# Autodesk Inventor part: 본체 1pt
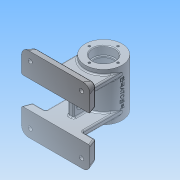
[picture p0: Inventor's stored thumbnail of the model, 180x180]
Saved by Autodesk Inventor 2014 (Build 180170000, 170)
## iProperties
Created: 2016-07
Part Number: 본체 1pt
Material: 알루미늄 6061
Document SubType Name: Modeling
Designer: NET
Density: 2.71 g/cm^3
Appearance: 알루미늄 - 평지
Mass: 499.72 g
Surface Area: 539.14 cm^2
Volume: 184.399 cm^3
Author: NET
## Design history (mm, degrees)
sketch "스케치1"
  geometry: C1 r 27 at (0, 0); 1 further point
  constraints: 1 centre point, 1 coincident
  dimensions: "d0" = 54 diameter of C1
extrude "돌출1" new body sketch "스케치1" stored distance "d1" = 70; taper "d2" = 0 deg
sketch "스케치2"
  geometry: C1 r 27 at (0, 0) reference; C2 r 16 at (0, 0)
  constraints: 1 centre point, 1 coincident
  dimensions: "d3" = 32 diameter of C2
extrude "돌출2" cut sketch "스케치2" distance "d4" = 12; taper "d5" = 0 deg
sketch "스케치3"
  geometry: C1 r 22 at (0, 0); 1 further point
  constraints: 1 centre point, 1 coincident
  dimensions: "d6" = 44 diameter of C1
extrude "돌출3" cut sketch "스케치3" stored distance "d7" = 42; taper "d8" = 0 deg
sketch "스케치4"
  geometry: C1 r 16 at (0, 0) reference; C2 r 14 at (0, 0)
  constraints: 1 centre point, 1 coincident
  dimensions: "d9" = 28 diameter of C2
extrude "돌출4" cut sketch "스케치4" stored distance "d10" = 42; taper "d11" = 0 deg
node "작업 평면2"
sketch "스케치5"
  geometry: L1 (-50, 55)-(50, 55); L2 (50, 55)-(50, 20); L3 (50, 20)-(-50, 20); L4 (-50, 20)-(-50, 55); L5 (-50, -20)-(50, -20); L6 (50, -20)-(50, -55); L7 (50, -55)-(-50, -55); L8 (-50, -55)-(-50, -20); L9 (-27, -20)-(27, -20); L10 (27, -20)-(27, -28); L11 (27, -28)-(-27, -28); L12 (-27, -28)-(-27, -20); L13 (-27, 20)-(27, 20); L14 (27, 20)-(27, 28); L15 (27, 28)-(-27, 28); L16 (-27, 28)-(-27, 20); 4 further points
  constraints: 32 end point, 8 parallel, 4 equal length, 4 horizontal, 4 midpoint, 4 perpendicular, 3 vertical alignment, 2 point on line
  dimensions: "d13" = 35 distance of L5.end L6.end; "d14" = 8 distance of L9.end L10.end; "d15" = 55 distance from line of point (0, 0) L1; "d16" = 100 distance between parallel lines of L2 L4; "d17" = 54 distance of L10.end L11.end; "d19" = 55 distance from line of point (0, 0) L7
extrude "돌출5" join sketch "스케치5" stored distance "d20" = 42; taper "d21" = 0 deg
sketch "스케치6"
  geometry: L1 (-40, 55)-(40, 55); L2 (50, 45)-(50, -45); L3 (40, -55)-(-40, -55); L4 (-50, -45)-(-50, 45); A1 r 10 centre (-40, -45) between (-50, -45) and (-40, -55); A2 r 10 centre (-40, 45) between (-40, 55) and (-50, 45); A3 r 10 centre (40, 45) between (50, 45) and (40, 55); A4 r 10 centre (40, -45) between (40, -55) and (50, -45); 7 further points
  constraints: 8 end point, 8 point on circle, 8 point on line, 8 tangent, 4 centre point, 3 equal radius, 2 midpoint, 2 parallel, 1 horizontal, 1 horizontal alignment, 1 perpendicular, 1 vertical alignment
  dimensions: "d22" = 100 distance of point (50, -55) point (-50, -55); "d23" = 110 distance of point (50, 55) point (50, -55); "d68" = 10 radius of A1
extrude "돌출6" join sketch "스케치6" distance "d24" = 12; taper "d25" = -20 deg
sketch "스케치7"
  geometry: L1 (-50, -45)-(-50, 45) reference; L2 (50, 45)-(50, -45) reference; L3 (-50, 20)-(50, 20); L4 (50, 20)-(50, -20); L5 (50, -20)-(-50, -20); L6 (-50, -20)-(-50, 20); 5 further points
  constraints: 8 end point, 2 parallel, 2 point on line, 1 horizontal, 1 perpendicular
extrude "돌출7" cut sketch "스케치7" distance "d26" = 12; taper "d27" = 0 deg
node "작업 평면3"
sketch "스케치8"
  geometry: L1 (27, 35)-(-27, 35) reference; C1 r 5 at (0, 13); 1 further point
  constraints: 1 centre point, 1 vertical alignment
  dimensions: "d29" = 22 distance from line of L1 C1.centre; "d30" = 10 diameter of C1
extrude "돌출8" join sketch "스케치8" stored distance "d31" = 12; taper "d32" = 0 deg
node "작업 평면4"
sketch "스케치9"
  geometry: L1 (-50, -20)-(50, -20) reference; L2 (50, 20)-(-50, 20) reference; L3 (-4, 20)-(4, 20); L4 (4, 20)-(4, -20); L5 (4, -20)-(-4, -20); L6 (-4, -20)-(-4, 20); 3 further points
  constraints: 8 end point, 2 midpoint, 2 parallel, 2 point on line, 1 coincident, 1 horizontal, 1 perpendicular
  dimensions: "d34" = 8 distance between parallel lines of L4 L6
extrude "돌출9" join sketch "스케치9" stored distance "d35" = 12; taper "d36" = 0 deg
sketch "스케치10"
  geometry: L1 (0, 21.298)-(40, 21.298) reference; L2 (12, 10)-(28, 10); L3 (12, 6.5)-(28, 6.5); L4 (28, 13.5)-(12, 13.5); L5 (65, -22)-(40, -22) reference; A1 r 3.5 centre (12, 10) between (12, 13.5) and (12, 6.5); A2 r 3.5 centre (28, 10) between (28, 6.5) and (28, 13.5); 4 further points
  constraints: 8 end point, 4 point on circle, 4 tangent, 2 centre point, 2 midpoint, 2 parallel, 1 vertical alignment
  dimensions: "d37" = 3.5 radius of A2; "d38" = 23 dimension on A2 A1; "d39" = 32 distance from line of L5 point (20, 10)
extrude "돌출10" cut sketch "스케치10" stored distance "d40" = 12; taper "d41" = 0 deg
sketch "스케치11"
  geometry: L1 (0, 0)-(-15.898, -25.441); L2 (0, 0)-(0, -16.13)
  constraints: 4 end point, 1 vertical
  dimensions: "d42" = 30 distance of L1.start L1.end; "d43" = 32 deg angle of L2 L1
node "작업 평면5"
sketch "스케치12"
  geometry: C1 r 6 at (0, 0); 1 further point
  constraints: 1 centre point, 1 coincident
  dimensions: "d44" = 12 diameter of C1
extrude "돌출11" join sketch "스케치12" stored distance "d45" = 12; taper "d46" = 0 deg
hole "구멍1" diameter "d49" = 6; stored, may be unused: countersink angle "d53" = 90 deg, drill point angle "d55" = 118 deg; dims "d47" = 12.5, "d48" = 1, "d50" = 6, "d51" = 10, "d52" = 4, "d54" = 8
node "작업 평면6"
sketch "스케치13"
  geometry: L1 (27, -35)-(27, 35) reference; 2 further points
  constraints: 1 coincident, 1 other
  dimensions: "d63" = 27 distance from line of point (0, 0) L1 (derived); "d64" = 35 vertical distance of L1.end point (0, 0) (derived)
feature "엠보싱1" sketch "스케치13" dims "d0" = 54, "d9" = 28, "d65" = 0.5, "d66" = 0
fillet "모깎기1" dims "d67" = 2
fillet "모깎기2" dims "d75" = 2
hole "구멍2" diameter "d78" = 5.188; stored, may be unused: countersink angle "d82" = 90 deg, drill point angle "d84" = 118 deg; dims "d76" = 10, "d77" = 10, "d79" = 6, "d80" = 10, "d81" = 4, "d83" = 8
hole "구멍3" diameter "d87" = 5.188; stored, may be unused: countersink angle "d91" = 90 deg, drill point angle "d93" = 118 deg; dims "d85" = 10, "d86" = 10, "d88" = 6, "d89" = 10, "d90" = 4, "d92" = 8
sketch "스케치14"
  geometry: C1 r 16 at (0, 0) reference; 1 further point
  constraints: 1 horizontal alignment
  dimensions: "d94" = 21 distance of C1.centre point (-21, 0)
hole "구멍4" sketch "스케치14" at (-21, 0) diameter "d95" = 3.242; stored, may be unused: countersink angle "d99" = 90 deg, drill point angle "d101" = 118 deg; dims "d96" = 8, "d97" = 10, "d98" = 4, "d100" = 10
chamfer "모따기1" distance "d105" = 1; stored, may be unused: second distance "d106" = 2, angle "d107" = 45 deg
fillet "모깎기3" dims "d108" = 3, "d109" = 0.3
fillet "모깎기4" dims "d110" = 2
node "솔리드1"
mirror "대칭1"
pattern_linear "직사각형 패턴2" dims "d71" = 85, "d74" = 75
pattern_circular "원형 패턴1" dims angle "d103" = 360 deg
mirror "대칭2"
node "작업 평면1"
node "작업 평면7"
other parameters: "d33" = -48
